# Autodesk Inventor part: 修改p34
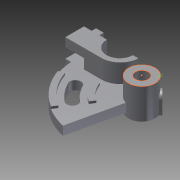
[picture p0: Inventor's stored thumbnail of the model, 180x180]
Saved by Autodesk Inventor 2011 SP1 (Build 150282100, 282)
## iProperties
Created: 2014-03
Part Number: 修改p34
Document SubType Name: Modeling
Designer: Administrator
Density: 1 g/cm^3
Author: Administrator
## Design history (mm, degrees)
sketch "草图1"
  geometry: C1 r 12 at (0, 0); C2 r 6 at (0, 0); 1 further point
  constraints: 2 centre point, 2 coincident
  dimensions: "d0" = 24 diameter of C1; "d1" = 12 diameter of C2
extrude "拉伸1" new body sketch "草图1" distance "d2" = 28; taper "d3" = 0 deg
sketch "草图2"
  geometry: L1 (-32, 12.447)-(-32, -7.57); L2 (-20, 12)-(-15, 12); L3 (-32, -4.576)-(-65, -4.576); L4 (-65, -4.576)-(-65, 12.424); L5 (-65, 12.424)-(-58, 12.424); L6 (-58, 12.424)-(-58, 16.424); L7 (-58, 16.424)-(-51, 16.424); L8 (-51, 16.424)-(-51, 12.424); L9 (-51, 12.424)-(-49.023, 12.424); L10 (-49.023, 12.424)-(-43.993, 12.424); L11 (-15, 12)-(-14.983, 12); C1 r 6 at (0, 0) reference; A1 r 12 centre (-32, 12) between (-43.993, 12.424) and (-20, 12); A2 r 17.023 centre (-32, 12.447) between (-32, -4.576) and (-14.983, 12)
  constraints: 22 end point, 6 parallel, 4 point on circle, 3 perpendicular, 2 centre point, 2 point on line, 1 coincident, 1 collinear, 1 tangent, 1 vertical
  dimensions: "d4" = 32 distance from line of C1.centre L1; "d5" = 24 diameter of A1; "d6" = 5 distance of L2.start L2.end; "d7" = 33 distance of L3.start L3.end; "d8" = 17 distance of L3.end L4.end; "d9" = 7 distance of L4.end L5.end; "d10" = 4 distance of L5.end L6.end; "d11" = 7 distance of L6.end L7.end
extrude "拉伸2" join sketch "草图2" distance "d12" = 25; taper "d13" = 0 deg
sketch "草图3"
  geometry: L1 (0, 0)-(-25, 0) reference; L2 (-17, 25)-(-8, 25); L3 (-8, 25)-(-8, 0); L4 (-8, 0)-(-17, 0); L5 (-17, 0)-(-17, 25); 2 further points
  constraints: 8 end point, 2 midpoint, 2 parallel, 1 horizontal, 1 perpendicular
  dimensions: "d14" = 9 distance of L2.start L2.end; "d15" = 25 distance of L2.end L3.end
extrude "拉伸3" cut sketch "草图3" distance "d16" = 17; taper "d17" = 0 deg
sketch "草图4"
  geometry: L1 (65, -4.576)-(32, -4.576) reference; L2 (2.693, -11.694)-(13.251, -58.518); L3 (14.983, 12)-(0, 12); C1 r 6 at (0, 0) reference; C2 r 12 at (0, 0) reference; A1 r 17.023 centre (32, 12.447) between (14.983, 12) and (32, -4.576) reference; A2 r 12 centre (0, 0) between (2.693, -11.694) and (0, 12) reference; A3 r 60 centre (0, 0) between (13.251, -58.518) and (59.825, -4.576); 1 further point
  constraints: 4 end point, 4 point on circle, 1 centre point, 1 coincident, 1 point on line, 1 tangent
extrude "拉伸4" join sketch "草图4" distance "d19" = 8; taper "d20" = 0 deg
sketch "草图5"
  geometry: L1 (59.327, 2.623)-(53.656, 0.663); L2 (59.515, 2.145)-(54.029, -0.287); L3 (61.811, -0.506)-(58.621, -5.588); L4 (36.719, -5.19)-(31.993, -6.823); L5 (49.088, -20.777)-(46.43, -25.013); L6 (43.927, -29)-(43.737, -29.304); L7 (38.421, -37.774)-(38.301, -37.965); L8 (35.763, -42.009)-(33.105, -46.244); L9 (13.014, -13.381)-(8.288, -15.015); L10 (28.526, -11.592)-(28.432, -11.634); L11 (19.342, -15.663)-(19.289, -15.686); A1 r 60 centre (65, 4.576) between (5.175, 0) and (51.749, -53.943) reference; A2 r 12 centre (65, 4.576) between (65, 16.576) and (62.307, -7.118) reference; A3 r 6 centre (65, 4.576) between (61.811, -0.506) and (59.327, 2.623) reference; A4 r 55 centre (65, 4.576) between (13.014, -13.381) and (35.763, -42.009); A5 r 40 centre (65, 4.576) between (28.054, -10.754) and (45.289, -30.23); A6 r 35 centre (65.074, 4.609) between (31.993, -6.823) and (46.43, -25.013); A7 r 30 centre (65.074, 4.609) between (36.719, -5.19) and (49.088, -20.777); A8 r 5.023 centre (23.934, -13.627) between (28.83, -12.504) and (19.342, -15.663); A9 r 5.292 centre (41.114, -33.483) between (37.071, -36.897) and (45.289, -30.23); A10 r 50 centre (65, 4.576) between (19.289, -15.686) and (37.071, -36.897)
  constraints: 28 point on circle, 22 end point, 7 centre point, 4 coincident
  dimensions: "d21" = 110 diameter of A4; "d23" = 80 diameter of A5; "d24" = 70 diameter of A6; "d25" = 60 diameter of A7
extrude "拉伸5" join sketch "草图5" distance "d27" = 2; taper "d28" = 0 deg
sketch "草图6"
  geometry: L1 (17, 0)-(33, 0) reference; L2 (7, 21)-(14, 21) reference; L3 (31.993, -6.823)-(36.719, -5.19) reference; A1 r 17.023 centre (33, 17.023) between (33, 0) and (50.017, 16.576) reference; A2 r 35 centre (65.074, 4.609) between (31.993, -6.823) and (46.43, -25.013) reference; A3 r 5.132 centre (25.074, -16.007) between (30.032, -14.68) and (21.202, -19.376); A4 r 5.06 centre (36.719, -30.334) between (32.937, -33.695) and (39.305, -25.985); A5 r 40 centre (65.074, 4.609) between (29.031, -12.738) and (40.443, -26.908); A6 r 50 centre (65.074, 4.609) between (20.083, -17.205) and (34.209, -34.728); A7 r 45 centre (65.074, 4.609) between (20.093, 5.924) and (20.31, 0); A8 r 40 centre (65.074, 4.609) between (25.165, 1.91) and (25.34, 0); A9 r 50 centre (65.074, 4.609) between (112.332, 20.939) and (112.311, 21)
  constraints: 24 point on circle, 7 centre point, 4 point on line, 3 coincident
extrude "拉伸6" cut sketch "草图6" stored distance "d32" = 2; taper "d33" = 0 deg
sketch "草图7"
  geometry: C1 r 6 at (0, 0) reference; 2 further points
  constraints: 2 other
node "工作平面1"
sketch "草图8"
  geometry: L1 (0, -28)-(-5, -28); L2 (-12, -28)-(12, -28) reference; L3 (-5, -28)-(-5, -16); L4 (-6, 0)-(6, 0) reference; L5 (5, -16)-(5, -28); L6 (5, -28)-(0, -28); C1 r 2.5 at (0, -16); A1 r 5 centre (0, -16) between (5, -16) and (-5, -16)
  constraints: 8 end point, 2 centre point, 2 perpendicular, 2 point on circle, 2 point on line, 1 coincident, 1 collinear, 1 tangent
  dimensions: "d35" = 5 distance of L1.start L1.end; "d36" = 12 distance of L1.end L3.end; "d37" = 5 diameter of C1
extrude "拉伸7" join sketch "草图8" stored distance "d38" = 2.5; taper "d39" = 0 deg
hole "Hole1" diameter "d42" = 5; stored, may be unused: countersink angle "d46" = 90 deg, drill point angle "d48" = 118 deg; dims "d40" = 10, "d41" = 10, "d43" = 6, "d44" = 4, "d45" = 2, "d47" = 8
node "实体1"
node "投影回路1"
